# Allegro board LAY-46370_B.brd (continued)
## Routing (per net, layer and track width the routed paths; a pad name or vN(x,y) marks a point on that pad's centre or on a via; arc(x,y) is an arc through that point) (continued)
SAI3_TXD: length 92.5
  TOP w0.102: J4.25 116.58,67 v1(117.27,67.7)
  TOP w0.109: v1(192.31,37.28) 192.11,37.28 191.24,36.42 R193.1
  BOTTOM w0.109: v1(117.27,67.7) 117.77,67.2 127.79,67.2 148.33,46.66 183.76,46.66 192.31,38.1 v1(192.31,37.28)
SAI3_TXFS: length 93.1
  TOP w0.102: v1(117.99,67.68) 116.91,66.6 J4.23
  TOP w0.109: R192.1 v1(192.3,36.7)
  BOTTOM w0.109: v1(192.3,36.7) 192.34,36.7 192.81,37.17 192.81,38.2 184.02,46.99 148.61,46.99 127.75,67.85 118.15,67.85 v1(117.99,67.68)
SAI5_RX3: length 20.2
  TOP w0.102: v1(127.83,63.65) 127.52,63.34 116.42,63.34 116.35,63.41 J4.7 ; U54.1 v1(127.89,57.17)
  L6_IN2 w0.114: v1(127.89,57.17) 127.89,63.58 v1(127.83,63.65)
SAI5_RXC: length 77.4
  TOP w0.109: J4.4 113.35,62.6 113.46,62.49 113.46,57.56 117.47,53.55 136.78,53.55 139.65,56.41 171.31,56.41 176.65,51.08 178.42,51.08 TP86.1 178.69,49.75 R297.1
SAI5_RXD0: length 67.4
  TOP w0.109: J4.1 121.55,62.2 TP82.1 128.78,61.25 131.78,61.25 135.06,57.97 173.49,57.97 174.03,58.51 175.59,58.51 176.77,59.69 R293.1
SAI5_RXD1: length 67
  TOP w0.109: J4.3 122.68,62.6 TP83.1 127.88,61.88 145.29,61.88 148.11,59.06 175.31,59.06 v1(175.36,59.01) ; R294.1 178.28,58.46 175.88,58.46 v1(175.36,57.93)
  L6_IN2 w0.127: v1(175.36,57.93) v1(175.36,59.01)
SAI5_RXD2: length 68.1
  TOP w0.109: v1(175.95,56.94) 176.17,57.15 R295.1 ; J4.5 123.8,63 TP84.1 126.97,62.5 145.31,62.5 148.31,59.49 175.57,59.49 v1(175.95,59.88)
  L6_IN2 w0.127: v1(175.95,56.94) v1(175.95,59.88)
SAI5_RXD3: length 55.4
  TOP w0.109: R296.1 173.32,55.88 171.82,57.39 134.24,57.39 132.74,55.89 130.43,55.89 130.06,56.26 ; 130.06,56.26 129.69,55.89 126.35,55.89 TP85.1 ; 130.06,56.26 U54.2
SAI5_RXFS: length 79.8
  TOP w0.109: U58.5 177.59,48.69 170.24,56.05 139.87,56.05 136.92,53.09 117.14,53.09 112.87,57.37 J4.2
SD1_DATA4: length 48.1
  TOP w0.109: J2.91 112.73,107.1 112.86,106.97 112.86,103.12 106.99,97.25 106.99,89.89 v1(109.06,87.83)
  BOTTOM w0.109: U3.3 131.54,84.43 130.88,83.77 121.92,83.77 121.26,84.43 116.72,84.43 113.07,88.07 109.3,88.07 v1(109.06,87.83)
SD1_DATA5: length 47.3
  TOP w0.109: J2.93 113.13,102.83 107.41,97.11 107.41,90.11 v1(109.04,88.48)
  BOTTOM w0.109: v1(109.04,88.48) 113.04,88.48 116.64,84.88 129.99,84.88 130.1,84.77 R41.2 130.9,84.3 131.53,84.93 U3.4
SD2_CLK: length 99.5
  TOP w0.109: v1(150.2,127.91) 150.2,127.79 149.91,127.5 148.93,127.5 148.93,127.5 148.21,127.5 111.28,90.57 111.28,81.36 111.63,81 J4.96
  BOTTOM w0.109: R155.1 179.1,129.05 177.49,127.43 150.68,127.43 v1(150.2,127.91)
SD2_CMD: length 101.2
  TOP w0.109: v1(148.48,127.07) 148.24,127.07 112.54,91.37 112.54,87.69 112.22,87.37 112.22,81.55 112.36,81.4 J4.98
  BOTTOM w0.109: R154.1 184.72,131.72 180.12,127.12 148.53,127.12 v1(148.48,127.07)
SD2_DATA0: length 97.9
  TOP w0.109: J4.91 117.12,80.2 118.16,81.25 118.16,94.46 v1(151.64,127.94)
  BOTTOM w0.109: v1(151.64,127.94) 177.39,127.94 178.02,128.57 178.02,129.35 177.92,129.45 177.6,129.45 177.5,129.55 177.5,129.75 177.6,129.86 177.92,129.86 178.02,129.96 178.02,130.16 177.92,130.26 177.6,130.26 177.5,130.36 177.5,130.57 177.6,130.67 177.92,130.67 178.02,130.77 178.02,130.97 177.92,131.07 177.6,131.07 177.5,131.18 177.5,131.38 177.6,131.48 177.92,131.48 178.02,131.58 178.02,131.79 177.92,131.89 177.6,131.89 177.5,131.99 177.5,132.19 177.6,132.29 177.92,132.29 178.02,132.4 R156.1
SD2_DATA1: length 97.9
  TOP w0.109: v1(150.95,127.95) 150.95,127.64 117.8,94.49 117.8,81.43 116.98,80.6 J4.93
  BOTTOM w0.109: R157.1 176.95,130.67 176.79,130.5 176.43,130.5 175.53,131.4 175.39,131.4 175.24,131.26 175.24,131.11 176.14,130.22 176.14,130.07 176,129.93 175.85,129.93 174.96,130.83 174.81,130.83 174.67,130.68 174.67,130.54 175.56,129.64 175.56,129.19 174.76,128.39 151.39,128.39 v1(150.95,127.95)
SD2_DATA2: length 101.1
  TOP w0.109: v1(148.46,125.83) 148.23,125.83 117.45,95.04 117.45,81.53 116.92,81 J4.95
  BOTTOM w0.109: R158.1 186.88,132.44 180.97,126.53 150.68,126.53 149.97,125.83 v1(148.46,125.83)
SD2_DATA3: length 100.2
  TOP w0.109: J4.97 116.92,81.4 117.14,81.63 117.14,95.36 148.19,126.41 v1(148.47,126.41)
  BOTTOM w0.109: R159.1 185.81,131.98 180.66,126.83 148.91,126.83 148.49,126.41 v1(148.47,126.41)
SD2_NCD: length 104
  TOP w0.102: TP40.1 v1(149.2,128.81)
  TOP w0.109: J4.94 111.56,80.6 110.91,81.25 110.91,90.7 148.17,127.96 TP40.1
  BOTTOM w0.109: J11.9 175.59,134.46 TVS1.2 174.81,134.35 174.28,133.82 174.28,129.17 173.92,128.81 168.63,128.81 168.53,128.92 168.53,129.31 168.43,129.41 168.22,129.41 168.12,129.31 168.12,128.92 168.02,128.81 167.82,128.81 167.72,128.92 167.72,129.31 167.61,129.41 167.41,129.41 167.31,129.31 167.31,128.92 167.21,128.81 167.01,128.81 166.9,128.92 166.9,129.31 166.8,129.41 166.6,129.41 166.5,129.31 166.5,128.99 166.4,128.89 149.27,128.89 v1(149.2,128.81)
SD2_RESET_B: length 2
  TOP w0.102: TP62.1 117.25,79.25 116.48,79.25 116.32,79.4 J4.87
SPDIF_EXT_CLK: length 38
  TOP w0.102: v1(115.26,88.41) 113.88,87.04 113.88,69.2 113.68,69 J4.36
  BOTTOM w0.109: U3.9 116.15,87.43 115.26,88.32 v1(115.26,88.41)
SPDIF_RX: length 21.7
  TOP w0.102: J4.34 113.8,68.6 114.15,68.95 114.15,82.6 v1(114.39,82.83)
  BOTTOM w0.102: v1(114.39,82.83) 114.35,82.87 110.49,82.87 TP12.1 109.97,82.56 109.97,83.71 110.07,83.82 U52.4
SPDIF_TX: length 21.3
  TOP w0.102: J4.32 114,68.2 114.39,68.59 114.39,82 115.3,82.91 v1(115.3,84.09)
  BOTTOM w0.102: U52.1 113.01,84.15 TP11.1 115.24,84.15 v1(115.3,84.09)
SPK_LN: length 3.2
  TOP w0.203: R208.1 187.16,27.18 188.8,28.82 U50.23
SPK_LP: length 4.1
  TOP w0.203: R206.1 188.65,25.28 190.21,26.84 U50.25
SPK_RN: length 2.7
  TOP w0.203: U50.19 189,30.82 188.85,30.97 187.42,30.97 R203.1
SPK_RP: length 2.9
  TOP w0.203: U50.22 188.83,29.32 187.76,28.25 R202.1
SPKOUTLN: length 7.7
  TOP w0.203: R208.2 185.3,27.18 C201.1 185.29,26.74 185.1,26.55 183.89,26.55 183.24,27.2 C199.2 182.07,27.2 CON1.4
SPKOUTLP: length 18.8
  TOP w0.203: C198.2 188.66,23.49 R206.2 188.48,23.51 185.91,26.08 183.52,26.08 183.15,26.45 C199.1 182.47,26.45 182.15,26.13 182.15,24.69 181.38,23.92 179.82,23.92 178.72,25.02 178.72,26.4 CON1.3
SPKOUTRN: length 6.9
  TOP w0.203: CON1.2 180.49,30.17 C195.2 183.71,30.17 183.96,29.92 185.06,29.92 185.24,30.11 C196.1 185.26,30.63 R203.2
SPKOUTRP: length 12.8
  TOP w0.203: R202.2 186.33,28.25 C194.2 185.29,29 184.88,29.42 C195.1 181.32,29.42 181.08,29.18 179.28,29.18 178.68,29.79 178.68,31.44 CON1.1
SS_RXN1: length 8.7
  TOP w0.102: U18.1 50.32,18.07 50.24,18.15 50.24,18.34 50.35,18.44 51.18,18.44 51.72,17.91 51.72,14.63 51.09,14 50.34,14 49.89,13.55 49.89,13.18 49.69,12.98 49.69,12.94 49.6,12.84 U19.C2
SS_RXN2: length 8.8
  TOP w0.102: v1(48.58,13.34) 48.72,13.19 48.72,12.85 U19.C4 ; U18.16 51.16,17.25 v1(51.22,17.3)
  BOTTOM w0.102: v1(48.58,13.34) 48.58,13.43 48.74,13.58 48.74,13.92 48.96,14.15 50.88,14.15 51.19,14.46 51.19,15.09 50.21,16.07 50.21,16.92 50.57,17.28 50.86,17.28 50.88,17.3 v1(51.22,17.3)
SS_RXP1: length 9.4
  TOP w0.102: U18.2 49.92,18.07 50.03,18.17 50.03,18.43 50.26,18.66 51.27,18.66 51.93,18 51.93,14.54 51.18,13.79 50.43,13.79 50.11,13.46 50.11,12.89 U19.C1
SS_RXP2: length 8.7
  TOP w0.102: v1(51.22,16.67) 51.16,16.67 50.98,16.85 U18.15 ; v1(49.16,13.34) 49.05,13.22 49.05,13.01 49.2,12.86 U19.C3
  BOTTOM w0.102: v1(49.16,13.34) 49.16,13.42 48.95,13.63 48.95,13.83 49.05,13.93 50.97,13.93 51.41,14.37 51.41,15.18 50.43,16.16 50.43,16.83 50.66,17.06 50.83,17.06 v1(51.22,16.67)
SS_TXN1: length 5.2
  TOP w0.102: v1(46.29,13.4) 46.29,13.34 46.23,13.29 U16.C3 ; v1(45.38,16.71) 45.8,16.71 C48.1
  BOTTOM w0.102: v1(46.29,13.4) 46.29,13.51 46.1,13.69 46.1,16.29 45.88,16.51 45.58,16.51 v1(45.38,16.71)
SS_TXN2: length 9.5
  TOP w0.102: C53.1 46.02,18.5 45.93,18.59 45.32,18.59 44.72,17.98 44.72,15.18 45.09,14.81 46.81,14.81 47.31,14.31 47.31,13.65 46.94,13.28 46.94,13.03 46.95,13.03 46.95,13.02 47.03,12.93 U16.C1
SS_TXP1: length 5.1
  TOP w0.102: v1(45.7,13.4) 45.9,13.2 45.9,12.9 U16.C4 ; v1(45.36,16.13) 45.51,16.27 45.68,16.27 46.03,15.93 C50.1
  BOTTOM w0.102: v1(45.36,16.13) 45.53,16.3 45.79,16.3 45.89,16.2 45.89,13.69 45.7,13.51 v1(45.7,13.4)
SS_TXP2: length 9.5
  TOP w0.102: C52.1 45.74,18.8 45.23,18.8 44.5,18.07 44.5,15.09 45,14.59 46.72,14.59 47.09,14.22 47.09,13.74 46.72,13.37 46.72,13.02 46.63,12.93 U16.C2
SSRXN1: length 15.7
  TOP w0.102: v1(50.08,10.34) 50.08,10.41 50.29,10.61 50.29,10.76 49.78,11.27 49.78,11.73 49.6,11.91 U19.A2
  BOTTOM w0.102: J6.B10 43.17,5.94 43.17,5.45 43.39,5.23 49.52,5.23 50.66,6.38 50.66,8.19 50.29,8.57 50.29,9.31 50.2,9.4 50.01,9.4 49.92,9.49 49.92,9.67 50.01,9.76 50.2,9.76 50.29,9.85 50.29,10.08 50.08,10.29 v1(50.08,10.34)
SSRXN2: length 4.8
  TOP w0.102: U19.A4 48.8,11.85 48.88,11.76 48.88,11.6 48.89,11.6 48.89,10.98 46.98,9.07 46.98,8.75 46.83,8.61 J6.A10
SSRXP1: length 15.8
  TOP w0.102: U19.A1 50,11.35 50.5,10.85 50.5,10.56 50.67,10.4 v1(50.67,10.34)
  BOTTOM w0.102: v1(50.67,10.34) 50.51,10.18 50.51,8.66 50.88,8.28 50.88,6.29 49.61,5.02 43.3,5.02 42.96,5.36 42.96,5.98 J6.B11
SSRXP2: length 4.8
  TOP w0.102: J6.A11 47.33,8.61 47.19,8.75 47.19,8.98 49.1,10.89 49.1,11.6 49.11,11.6 49.11,11.81 49.2,11.9 U19.A3
SSTXN1: length 6.4
  TOP w0.102: v1(46.3,11.3) 46.17,11.43 46.17,11.83 46.23,11.89 U16.A3 ; v1(43.44,8.99) 43.25,8.8 43.25,8.45 43.33,8.37 J6.A3
  BOTTOM w0.102: v1(43.44,8.99) 43.26,9.18 43.26,9.58 43.8,10.13 45.34,10.13 46.12,10.9 46.12,11.12 v1(46.3,11.3)
SSTXN2: length 9.4
  TOP w0.102: v1(47.13,10.46) 46.95,10.64 46.95,11.77 47.03,11.86 U16.A1
  BOTTOM w0.102: v1(47.13,10.46) 47.13,10.61 46.96,10.78 46.96,11.37 47.04,11.46 47.91,11.46 48,11.37 48,8.6 46.98,7.58 46.98,6.54 J6.B3
SSTXP1: length 6.4
  TOP w0.102: v1(42.86,8.99) 42.96,8.89 42.96,8.42 42.83,8.3 J6.A2 ; v1(45.72,11.3) 45.89,11.48 45.89,11.87 45.83,11.93 U16.A4
  BOTTOM w0.102: v1(42.86,8.99) 43.04,9.17 43.04,9.67 43.71,10.34 45.25,10.34 45.9,10.99 45.9,11.12 v1(45.72,11.3)
SSTXP2: length 10.2
  TOP w0.102: U16.A2 46.63,11.86 46.73,11.76 46.73,10.65 v1(46.54,10.46)
  BOTTOM w0.102: J6.B2 47.19,6.54 47.19,7.49 48.21,8.51 48.21,11.46 48,11.68 46.95,11.68 46.74,11.46 46.74,10.78 46.54,10.59 v1(46.54,10.46)
ST_FT_USB_DN: length 6.3
  TOP w0.102: U60.7 12.27,14.79 12.42,14.65 12.42,14.25 12.82,13.84 12.82,12.33 13.24,11.91 14.47,11.91 14.6,11.78 14.6,11.62 R327.2
ST_FT_USB_DP: length 6.4
  TOP w0.102: R328.2 15.21,11.21 14.82,11.61 14.82,11.87 14.56,12.12 13.33,12.12 13.03,12.42 13.03,13.93 12.63,14.34 12.63,14.65 12.77,14.79 U60.8
SUSCLK_3V3: length 16.8
  TOP w0.254: v1(137.93,86.75) 138.08,86.75 138.15,86.68 TP99.1 138.8,87.7 139.44,88.35 151.24,88.35 v1(151.45,88.55)
  BOTTOM w0.254: v1(151.45,88.55) 151.47,88.58 J10.50 ; R30.1 137.85,86.67 v1(137.93,86.75)
SW_BOOT_MODE0: length 57.3
  TOP w0.109: SW4.4 8.91,125.27 R287.1 8.5,125.26 8.4,125.16 8.4,81.51 6.75,79.86 6.75,77.41 8.02,76.14 11.07,76.14 v1(11.2,76)
  BOTTOM w0.109: U20.16 10.98,77.15 11.2,76.93 v1(11.2,76)
SW_BOOT_MODE1: length 56.7
  TOP w0.109: SW4.3 7.64,125.27 R288.1 7.99,125.25 8.13,125.11 8.13,81.9 6.38,80.15 6.38,77.13 7.83,75.68 v1(9.75,75.68)
  BOTTOM w0.109: U20.3 9.57,75.86 v1(9.75,75.68)
SW_BOOT_MODE2: length 49.8
  TOP w0.109: v1(7.37,82.18) 7.37,82.42 5.84,83.96 5.84,125.15 5.96,125.27 R289.1 6.37,125.27 SW4.2
  BOTTOM w0.109: v1(7.37,82.18) 9.17,80.38 U20.9
SW_BOOT_MODE3: length 52.2
  TOP w0.109: SW4.1 5.1,125.26 R290.1 5.45,125.25 5.59,125.12 5.59,83.41 6.73,82.27 v1(6.73,82.21)
  BOTTOM w0.109: U20.12 10.37,79.59 10.54,79.76 10.54,80.71 8.58,82.67 7.19,82.67 v1(6.73,82.21)
SYS_NRST: length 187.5
  TOP w0.102: R406.2 12.82,133.28 12.96,133.14 D23.A
  TOP w0.109: v1(22.65,133.08) 21.54,134.19 15.7,134.19 14.65,133.14 D23.A ; J3.43 97.42,59.78 97.57,59.64 97.57,55.27 TP121.1 88.17,45.87 v1(88.17,45.66)
  L6_IN2 w0.114: v1(21.84,45.94) 21.84,55.74 24.02,57.92 v1(24.02,74.59) 25.07,75.64 25.07,118.29 24.53,118.83 24.53,126.06 22.57,128.02 22.57,133 v1(22.65,133.08)
  BOTTOM w0.102: v1(24.02,74.59) 23.93,74.5 R436.2
  BOTTOM w0.109: v1(88.17,45.66) 87.93,45.9 74.45,45.9 73.52,44.97 22.81,44.97 v1(21.84,45.94)
TCPC_NINT: length 116.9
  TOP w0.109: U11.10 29.85,18.72 v1(29.77,18.8) 29.59,18.8 TP22.1 ; v1(106.69,47.84) 107.47,48.63 107.47,58.54 107.02,58.99 J3.91
  L6_IN2 w0.114: v1(29.77,18.8) 29.77,22.51 37.01,29.75 v1(37.01,47.41)
  BOTTOM w0.109: v1(37.01,47.41) 37.44,47.84 106.69,47.84 v1(106.69,47.84)
TCPC_NINT1: length 100.4
  TOP w0.109: J3.93 107.42,59.91 107.28,59.76 107.28,59.3 107.83,58.74 107.83,48.27 v1(107.4,47.83) ; v1(41.53,29.96) 41.91,29.58 TP31.1 42.8,27.93 42.8,27.3 42.97,27.13 U17.10
  L6_IN2 w0.114: v1(41.53,47.34) v1(41.53,29.96)
  BOTTOM w0.109: v1(41.53,47.34) 106.9,47.34 v1(107.4,47.83)
TYPEC_EN_B: length 1.9
  TOP w0.102: U18.3 49.52,18.56 R40.1
UART2_RXD: length 117.6
  TOP w0.109: v1(76.51,45.42) 76.51,60.29 84.84,68.62 99.4,68.62 101.42,66.59 J3.64 ; R232.1 10.69,40.72 TP58.1 v1(10.33,42.11)
  BOTTOM w0.109: v1(76.51,45.42) 76,44.91 75.18,44.91 74.64,44.37 12.59,44.37 v1(10.33,42.11)
UART2_TXD: length 113.9
  TOP w0.109: R230.1 12.85,40.54 TP57.1 v1(13.38,42.11) ; J3.62 101.02,63.69 101.13,63.79 101.13,66.32 99.27,68.19 85.17,68.19 77.03,60.05 77.03,45.12 v1(76.5,44.59)
  BOTTOM w0.109: v1(76.5,44.59) 75.65,43.73 15,43.73 v1(13.38,42.11)
UART3_CTS: length 82.2
  TOP w0.102: J4.42 112.52,70.2 112.43,70.3 111.87,70.3 111.55,69.98 v1(111.55,69.82)
  TOP w0.109: U56.4 181.07,93.29 180.96,93.19 179.86,93.19 v1(179.09,92.41)
  BOTTOM w0.109: v1(111.55,69.82) 111.55,69.69 111.89,69.35 154.56,69.35 177.62,92.41 v1(179.09,92.41)
UART3_CTS_3V3: length 8.2
  TOP w0.109: J21.7 188.57,95.34 186.52,93.29 U56.8
UART3_RTS: length 83.7
  TOP w0.102: v1(110.97,69.82) 110.97,70.07 111.5,70.6 J4.44
  TOP w0.109: U56.5 180.21,92.89 v1(179.7,92.37)
  BOTTOM w0.109: v1(179.7,92.37) 178.97,91.64 177.54,91.64 154.86,68.96 111.71,68.96 110.97,69.7 v1(110.97,69.82)
UART3_RTS_3V3: length 8.5
  TOP w0.109: J21.11 186.19,90.26 183.55,92.89 U56.7
UART3_RXD: length 82.4
  TOP w0.102: v1(111.55,71.66) 111.59,71.66 112,71.25 112.31,71.25 112.47,71.4 J4.48
  TOP w0.109: U56.3 181.12,93.69 180.89,93.46 179.68,93.46 v1(179.23,93.91)
  BOTTOM w0.109: v1(179.23,93.91) 177.82,93.91 154.47,70.56 112.68,70.56 111.57,71.66 v1(111.55,71.66)
UART3_RXD_3V3: length 15.8
  TOP w0.109: J21.10 194.47,92.8 193.41,93.85 193.41,95.54 192.67,96.28 188.81,96.28 186.22,93.69 U56.9
UART3_TXD: length 83
  TOP w0.102: J4.46 111.28,71 v1(111.01,70.73)
  TOP w0.109: U56.2 180.95,94.09 180.91,94.05 v1(180,94.05)
  BOTTOM w0.109: v1(111.01,70.73) 111.95,70.73 112.43,70.25 154.92,70.25 178.12,93.46 179.4,93.46 v1(180,94.05)
UART3_TXD_3V3: length 13.9
  TOP w0.109: U56.10 185.95,94.09 188.49,96.63 193.11,96.63 194.4,95.34 J21.8
UART4_RXD: length 121.2
  TOP w0.109: v1(8.81,42.11) TP61.1 9.6,40.28 R233.1 ; J3.68 102.22,66.93 99.73,69.42 84.18,69.42 75.44,60.68 v1(75.44,45.41)
  BOTTOM w0.109: v1(75.44,45.41) 75.24,45.41 74.51,44.67 11.37,44.67 v1(8.81,42.11)
UART4_TXD: length 117.2
  TOP w0.109: v1(11.86,42.11) TP60.1 11.78,40.99 R231.1 ; J3.66 101.82,66.76 99.56,69.02 84.45,69.02 75.96,60.53 75.96,44.93 v1(75.48,44.45)
  BOTTOM w0.109: v1(75.48,44.45) 75.07,44.04 13.78,44.04 v1(11.86,42.11)
USB1_CC1: length 18.4
  TOP w0.109: U15.A2 40.62,12.39 40.02,12.99 40.02,15.45 40.58,16.02 42.23,16.02 42.69,16.47 42.69,21.17 41.7,22.16 TP28.1 42.18,24.87 43.15,24.87 43.62,25.34 U17.13
USB1_CC1_CN: length 6.4
  TOP w0.109: J6.A5 44.33,8.5 44.53,8.69 44.53,9.45 43.35,10.63 41.71,10.63 41.18,11.16 41.18,11.83 U15.A1
USB1_CC2: length 17.3
  TOP w0.109: U17.14 44.47,25.06 43.8,24.39 TP30.1 42.42,23.29 42.42,22.08 43.08,21.42 43.08,15.37 43.34,15.11 43.34,12.13 42.74,11.53 42.33,11.53 42.14,11.71 U15.C1
  TOP w0.203: U15.C1 U15.C2 U15.B2
USB1_CC2_CN: length 17.1
  TOP w0.102: U15.B1 41.72,11.97 v1(41.72,11.47)
  L3_IN1 w0.114: J6.B5 45.88,4.12 45.12,3.35 41.65,3.35 39.53,5.47 39.53,8.23 41.72,10.41 v1(41.72,11.47)
USB1_DN: length 120
  TOP w0.102: v1(77.83,111.99) 78.02,111.81 78.02,111.05 77.89,110.92 J1.36 ; U75.C1 44.56,12.95 44.42,13.08 44.42,13.51 44.49,13.58 44.71,13.58 44.81,13.68 v1(44.81,13.9)
  L6_IN2 w0.089: v1(77.83,111.99) 78.07,112.23 78.07,112.53 77.97,112.63 77.54,112.63 77.08,112.16 77.08,110.08 75.88,108.89 75.88,105.29 75.31,104.71 69.85,104.71 61.26,96.12 61.26,59.18 47.67,45.59 47.67,22.61 44.44,19.39 44.44,14.37 44.53,14.28 44.73,14.28 44.81,14.2 v1(44.81,13.9)
USB1_DN_CN: length 6.4
  TOP w0.102: J6.A7 45.33,8.79 v1(45.34,8.8) 45.34,9.99 44.56,10.77 U75.A1
  L3_IN1 w0.114: v1(45.34,8.8) 45.34,7.76 44.68,7.1 J6.B7
USB1_DP: length 120.1
  TOP w0.102: U75.C2 44.16,13.83 v1(44.23,13.9) ; v1(78.42,112) 78.23,111.81 78.23,111.25 78.29,111.2 J1.38
  L6_IN2 w0.089: v1(78.42,112) 78.29,112.13 78.29,112.62 78.06,112.84 77.45,112.84 76.86,112.25 76.86,110.17 75.67,108.98 75.67,105.37 75.22,104.93 69.76,104.93 61.04,96.21 61.04,59.27 47.45,45.68 47.45,22.7 44.23,19.48 v1(44.23,13.9)
USB1_DP_CN: length 6.5
  TOP w0.102: J6.B6 45.55,6.95 45.77,7.18 45.77,7.35 45.63,7.49 44.95,7.49 44.83,7.6 J6.A6 44.83,8.94 45.12,9.23 45.12,9.9 44.34,10.68 44.34,11.76 44.16,11.94 U75.A2
USB1_OTG_VBUS: length 2.3
  TOP w0.254: J6.B4 46.33,7 J6.A9 ; J6.A4 43.83,7 J6.B9
  vias: v1(40.1,11.41) v1(40.1,10.64) v1(40.1,9.76)
USB1_OTG_VBUS_F: length 0.9
  TOP w0.254: U17.15 44.87,24.75 v1(44.97,24.65)
  vias: v1(36.53,14.19) v1(36.52,13.51) v1(37.44,14.17) v1(37.44,13.52) v1(56.41,36.93) v1(57.05,36.91) v1(57.7,36.9) v1(58.33,36.91) v1(72.42,35.35) v1(72.42,34.72) v1(72.44,34.08)
USB1_RXN: length 113.9
  TOP w0.102: v1(50.41,15.15) 50.32,15.23 U18.14 ; v1(76.61,106.25) 76.79,106.42 76.79,107.13 76.69,107.22 J1.29
  L6_IN2 w0.089: v1(76.61,106.25) 76.61,104.76 75.96,104.11 70.42,104.11 62.31,96 62.31,58.64 48.78,45.11 48.78,19.95 47.04,18.21 47.04,15.17 48.28,13.92 49.84,13.92 50.29,14.38 50.29,15.03 50.41,15.15 v1(50.41,15.15)
USB1_RXP: length 113.8
  TOP w0.102: v1(77.2,106.25) 76.99,106.46 76.99,107.15 77.09,107.25 J1.31 ; v1(49.82,15.13) 49.82,15.21 50.11,15.5 50.11,15.76 49.92,15.94 U18.13
  L6_IN2 w0.089: v1(49.82,15.13) 50.08,14.87 50.08,14.47 49.75,14.14 48.37,14.14 47.26,15.26 47.26,18.13 49,19.86 49,45.02 62.52,58.55 62.52,95.91 70.51,103.9 76.05,103.9 76.83,104.67 76.83,105.8 76.92,105.88 77.18,105.88 77.27,105.97 77.27,106.18 v1(77.2,106.25)
USB1_SBU1: length 1.5
  TOP w0.102: TP24.1 45.83,9.45 J6.A8
USB1_SBU2: length 8.5
  TOP w0.102: v1(44.3,3.93) 38.7,3.93 TP25.1
  L3_IN1 w0.114: v1(44.3,3.93) 44.3,6.24 J6.B8
USB1_SS_SEL: length 109.2
  TOP w0.102: U18.12 49.52,15.44 49.19,15.11 49.19,14.86 v1(47.82,13.49)
  TOP w0.109: J3.97 108.22,59.86 108.25,59.83 108.25,47.96 v1(108.14,47.85)
  L6_IN2 w0.114: v1(53.85,46.51) 53.22,45.89 53.22,16.19 49.93,12.89 48.39,12.89 47.82,13.46 v1(47.82,13.49)
  BOTTOM w0.102: R38.1 47.82,13.71 v1(47.82,13.49)
  BOTTOM w0.109: v1(108.14,47.85) 107.22,46.93 54.27,46.93 v1(53.85,46.51)
USB1_TXN: length 109.8
  TOP w0.102: v1(48.1,15.05) 48.1,15.07 48.31,15.27 48.31,15.82 48.32,15.84 U18.9 ; v1(77.81,105.03) 77.81,105.04 78.03,105.26 78.03,107.08 77.89,107.22 J1.35
  L6_IN2 w0.089: v1(77.81,105.03) 77.95,104.88 77.95,104.87 77.99,104.83 77.99,104.42 76.88,103.31 71.08,103.31 63.75,95.98 63.75,57.87 51.55,45.67 51.55,21.38 48.27,18.1 48.27,15.22 v1(48.1,15.05)
USB1_TXP: length 109.8
  TOP w0.102: v1(48.68,15.05) 48.52,15.21 48.52,15.73 48.72,15.93 U18.10 ; J1.37 78.29,107.06 78.24,107.01 78.24,105.18 v1(78.39,105.03)
  L6_IN2 w0.089: v1(78.39,105.03) 78.21,104.85 78.21,104.34 76.97,103.09 71.16,103.09 63.96,95.89 63.96,57.78 51.76,45.58 51.76,21.29 48.49,18.01 48.49,15.25 v1(48.68,15.05)
USB1_TYPEC_EN_B: length 138.4
  TOP w0.102: v1(111.51,79.82) 111.99,80.3 112.32,80.3 112.42,80.2 J4.92 ; v1(51.11,19.82) 50.82,20.11 R40.2
  L6_IN2 w0.114: v1(111.51,79.82) 111.51,79.54 114.76,76.3 122.39,76.3 123.01,75.68 123.01,49.41 122.44,48.84 122.44,30.27 116.76,24.59 113.29,24.59 v1(109.81,21.12)
  BOTTOM w0.109: v1(109.81,21.12) 108.53,19.83 72.2,19.83 70.73,21.31 52.61,21.31 v1(51.11,19.82)
USB1_VBUS_3V3: length 119.4
  TOP w0.203: v1(79.5,111.4) 79.49,111.39 J1.44
  TOP w0.381: U12.1 67.41,34.99 67.06,34.63 R48.2
  TOP w0.457: R48.2 65.93,33.98 v1(65.88,34.03)
  L6_IN2 w0.457: v1(45.48,43.24) 45.48,46.42 56.88,57.82 56.88,96.91 v1(68.09,108.12)
  BOTTOM w0.457: v1(68.09,108.12) 68.12,108.14 73.84,108.14 75.72,110.02 78.07,110.02 79.44,111.4 v1(79.5,111.4) ; v1(45.48,43.24) 64.5,43.24 65.88,41.86 v1(65.88,34.03)
USB1_VBUS_IN: length 7.5
  TOP w0.254: v1(56.26,28.22) C43.2
  L6_IN2 w0.254: v1(56.26,28.22) 55.57,28.91 v1(55.57,33.9)
  vias: v1(54.88,35.65) v1(54.89,34.89) v1(54.89,33.93) v1(55.51,35.62) v1(55.51,34.83)
USB2_DN: length 3.6
  TOP w0.102: J1.54 81.49,111.07 81.6,111.18 81.6,111.78 v1(81.45,111.93)
  BOTTOM w0.102: R301.1 81.6,111.25 81.6,111.77 81.58,111.79 81.58,111.8 v1(81.45,111.93) 81.45,112.38 R299.2
USB2_DP: length 3.6
  TOP w0.102: J1.56 81.89,111.12 81.82,111.19 81.82,111.71 v1(82.04,111.93)
  BOTTOM w0.102: R300.1 82.21,110.81 81.8,111.23 81.8,111.69 v1(82.04,111.93) 82.04,112.49 R298.2
USB2_H_DN: length 107.1
  TOP w0.102: U77.C1 65.64,21.14 65.55,21.23 65.55,21.83 65.74,22.02 v1(65.74,22.06)
  L6_IN2 w0.089: v1(68.15,98.21) 68,98.07 68,97.6 65.33,94.94 65.33,28.53 65.55,28.31 65.55,24.07 65.64,23.98 65.73,23.98 65.82,23.89 65.82,23.71 65.73,23.62 65.64,23.62 65.55,23.53 65.55,23.35 65.64,23.27 65.73,23.27 65.82,23.18 65.82,23 65.73,22.91 65.64,22.91 65.55,22.82 65.55,22.25 v1(65.74,22.06)
  BOTTOM w0.102: v1(68.15,98.21) 67.94,98.42 67.94,104.23 71,107.29 74.78,107.29 76.43,108.95 78.43,108.95 80.5,111.02 80.5,112.41 80.26,112.65 80.26,114.36 80.7,114.8 81.21,114.8 81.59,114.43 81.59,113.8 81.22,113.42 R299.1
USB2_H_DP: length 107.2
  TOP w0.102: U77.C2 65.24,21.14 65.33,21.22 65.33,21.37 65.34,21.39 65.34,21.88 v1(65.15,22.06)
  L6_IN2 w0.089: v1(67.56,98.21) 67.78,97.99 67.78,97.69 65.12,95.03 65.12,28.44 65.34,28.22 65.34,22.25 v1(65.15,22.06)
  BOTTOM w0.102: v1(67.56,98.21) 67.73,98.38 67.73,104.32 70.91,107.5 74.69,107.5 76.34,109.16 78.34,109.16 80.29,111.11 80.29,112.32 80.04,112.56 80.04,114.45 80.61,115.02 81.3,115.02 81.81,114.52 81.81,113.84 R298.1
USB2_H_TXN: length 3
  TOP w0.102: C60.1 69.14,22.39 69.14,21.94 69.03,21.83 68.23,21.83 67.95,21.55 67.95,21.4 67.95,21.39 67.95,21.24 67.86,21.15 U21.C2
USB2_H_TXP: length 3
  TOP w0.102: U21.C1 68.26,21.16 68.17,21.25 68.17,21.39 68.17,21.4 68.17,21.47 68.32,21.61 69.12,21.61 69.36,21.85 69.36,22.39 C59.1
USB2_HOST_VBUS: length 4.6
  TOP w0.254: v1(60.17,17.96) 59.82,17.61 56.42,17.61 TP103.1
  vias: v1(60.87,17.95) v1(61.55,17.94)
USB2_PWR_EN: length 113.7
  TOP w0.102: J1.16 73.89,111.48 73.4,111.97 v1(73.37,111.97)
  TOP w0.109: v1(46.48,28.81) 51.87,28.81 54.24,26.43 54.99,26.43 55.6,27.04 57.29,27.04 57.77,26.55 R302.1
  L6_IN2 w0.114: v1(46.48,28.81) 46.11,29.19 46.11,46.15 57.8,57.85 57.8,94.14 69.31,105.65 74.37,105.65 74.76,106.04 74.76,110.63 73.42,111.97 v1(73.37,111.97)
USB2_RXN: length 96.5
  TOP w0.102: v1(79.88,105.66) 79.8,105.66 79.18,106.29 79.18,106.92 79.09,107.02 J1.41 ; v1(66.97,22.58) 67.15,22.4 67.15,21.4 67.15,21.39 67.15,21.27 67.06,21.18 U21.C4
  L6_IN2 w0.089: v1(66.97,22.58) 67.15,22.77 67.15,95.75 73.94,102.53 79.33,102.53 80.4,103.6 80.4,105.78 80.31,105.87 80.09,105.87 v1(79.88,105.66)
USB2_RXP: length 96.4
  TOP w0.102: J1.43 79.49,107.02 79.4,106.92 79.4,106.38 79.62,106.15 79.8,106.15 79.89,106.24 v1(79.89,106.25) ; U21.C3 67.46,21.15 67.37,21.23 67.37,21.39 67.37,21.4 67.37,22.4 v1(67.55,22.58)
  L6_IN2 w0.089: v1(67.55,22.58) 67.37,22.77 67.37,95.66 74.03,102.32 79.42,102.32 80.62,103.52 80.62,105.87 80.4,106.09 80.06,106.09 v1(79.89,106.25)
USB2_TXN: length 93.6
  TOP w0.102: v1(68.89,25.06) 68.89,24.97 69.1,24.76 69.1,23.95 69.1,23.95 C60.2 ; J1.47 80.29,107.02 80.38,106.92 80.38,106.1 80.63,105.86 80.89,105.6 81.05,105.6 v1(81.1,105.65)
  L6_IN2 w0.089: v1(81.1,105.65) 81.24,105.79 81.48,105.79 81.6,105.68 81.6,103.73 79.63,101.76 74.68,101.76 69.07,96.16 69.07,25.24 v1(68.89,25.06)
USB2_TXP: length 93.6
  TOP w0.102: J1.49 80.69,107.02 80.6,106.92 80.6,106.19 80.72,106.07 80.97,106.07 81.09,106.2 v1(81.09,106.25) ; C59.2 69.31,24.04 69.31,24.9 v1(69.47,25.06)
  L6_IN2 w0.089: v1(69.47,25.06) 69.29,25.24 69.29,96.07 74.77,101.55 79.72,101.55 81.82,103.64 81.82,105.77 81.53,106.05 81.25,106.05 81.09,106.21 v1(81.09,106.25)
USB2_VBUS_3V3: length 3.3
  TOP w0.203: J1.50 80.69,111.06 80.6,111.15 80.6,111.92 81.09,112.41 81.66,112.41 R66.2
USB_CC1: length 11.3
  TOP w0.102: U10.A2 24.93,12.34 24.82,12.44 24.82,15.14 25.17,15.48 28.05,15.48 TP19.1
  TOP w0.109: TP19.1 30.94,17.01 U11.13
USB_CC1_CN: length 152.2
  TOP w0.102: J5.A5 28.22,9.12 v1(28.23,9.13)
  L6_IN2 w0.114: SW3.3 19.87,150.1 26.9,143.07 26.9,73.43 35.92,64.42 35.92,31.93 28.83,24.85 28.83,9.73 v1(28.23,9.13)
USB_CC1_ESD: length 149.6
  TOP w0.109: U10.A1 v1(24.78,11.3)
  L6_IN2 w0.114: SW3.2 20.6,147.6 26.24,141.96 26.24,73.26 35,64.5 35,32.38 28.23,25.61 28.23,12.72 27.35,11.84 25.31,11.84 v1(24.78,11.3)
USB_CC2: length 9.1
  TOP w0.109: U11.14 31.79,16.75 29.98,14.95 TP21.1 26.77,11.59 26.43,11.59 26.21,11.8 U10.C1 U10.C2 U10.B2
USB_CC2_CN: length 165.9
  L6_IN2 w0.114: SW3.6 17.41,151.14 20.02,151.14 27.25,143.91 27.25,73.47 36.33,64.4 36.33,31.32 29.14,24.13 29.14,15.08 34.37,9.85 34.37,6.82 32.91,5.36 30.66,5.36 J5.B5
USB_CC2_ESD: length 154.2
  TOP w0.109: v1(25.53,11.37) 25.81,11.65 U10.B1
  L6_IN2 w0.114: v1(25.53,11.37) 27.63,11.37 28.52,12.26 28.52,25.08 35.48,32.04 35.48,64.46 26.56,73.39 26.56,142.43 20.14,148.84 17.61,148.84 SW3.5
USB_DBG_DN: length 5
  TOP w0.102: U62.A2 14.66,8.15 14.66,7.38 13.82,6.54 13.51,6.54 12.67,5.7 12.67,5.12 12.46,4.91 J23.2
USB_DBG_DP: length 5
  TOP w0.102: J23.3 13.11,4.89 12.9,5.1 12.9,5.61 13.61,6.32 13.92,6.32 14.89,7.29 14.89,8.22 U62.A1
USB_HOST_DN: length 21.3
  TOP w0.102: U77.A1 65.64,20.06 65.55,19.98 65.55,18.91 63.25,16.6 59.11,16.6 57.75,15.24 57.75,12.98 58.83,11.9 62.91,11.9 63.21,12.19 63.21,13.15 62.97,13.4 62.37,13.4 J7.2
USB_HOST_DP: length 21.2
  TOP w0.102: J7.3 63.52,13.11 63.43,13.02 63.43,12.1 63,11.68 58.74,11.68 57.53,12.89 57.53,15.32 59.02,16.82 63.16,16.82 65.33,19 65.33,19.81 65.33,19.82 65.33,19.92 65.24,20.01 U77.A2
USB_HOST_RXN: length 10.8
  TOP w0.102: v1(66.2,17.68) 66.2,17.74 66.58,18.12 66.58,19.13 67.15,19.7 67.15,19.83 67.15,19.84 67.15,19.94 67.06,20.03 U21.A4
  BOTTOM w0.102: J7.5 66.38,14.61 66.15,14.84 66.15,15.52 65.09,16.58 65.09,16.73 65.18,16.82 65.28,16.82 65.37,16.9 65.37,17.08 65.28,17.17 65.18,17.17 65.09,17.26 65.09,18.15 65.61,18.67 66.42,18.67 66.56,18.53 66.56,18.09 66.2,17.73 v1(66.2,17.68)
USB_HOST_RXP: length 10.9
  TOP w0.102: v1(66.78,17.68) 66.79,17.69 66.79,19.04 67.37,19.61 67.37,19.83 67.37,19.84 67.37,19.98 67.46,20.07 U21.A3
  BOTTOM w0.102: v1(66.78,17.68) 66.79,17.69 66.79,18.67 66.57,18.89 65.52,18.89 64.87,18.24 64.87,16.49 65.94,15.43 65.94,14.8 65.74,14.61 J7.6
USB_HOST_TXN: length 14
  TOP w0.102: U21.A2 67.86,20.07 67.95,19.98 67.95,19.84 67.95,19.83 67.95,19.31 v1(67.78,19.13)
  BOTTOM w0.102: J7.8 60.4,14.61 60.22,14.79 60.22,15.64 64.53,19.95 65.23,19.95 65.32,19.86 65.32,19.82 65.41,19.73 65.59,19.73 65.68,19.82 65.68,19.86 65.77,19.95 65.94,19.95 66.03,19.86 66.03,19.81 66.12,19.72 66.3,19.72 66.39,19.81 66.39,19.86 66.48,19.95 66.66,19.95 66.74,19.86 66.74,19.81 66.83,19.72 67.01,19.72 67.1,19.81 67.1,19.86 67.19,19.95 67.77,19.95 67.96,19.75 67.96,19.32 v1(67.78,19.13)
USB_HOST_TXP: length 14.1
  TOP w0.102: v1(68.36,19.13) 68.17,19.33 68.17,19.83 68.17,19.84 68.17,20 68.26,20.09 U21.A1
  BOTTOM w0.102: v1(68.36,19.13) 68.18,19.32 68.18,19.84 67.85,20.16 64.44,20.16 60,15.73 60,14.78 59.84,14.61 J7.9
USB_LD_NFLT: length 1.8
  TOP w0.109: U11.11 29.27,18.32 R447.1
USB_LD_NFLT1: length 1.7
  TOP w0.109: U17.11 42.83,26.73 R63.1
USB_PWR_VBUS_F: length 12.7
  TOP w0.203: R42.1 25.04,21.83 25.31,21.56 29.36,21.56 31.77,23.96 31.77,25.09
  TOP w0.254: 32.18,15.54 32.19,15.54 U11.15
  vias: v1(32.82,23.3) v1(33.23,14.12) v1(33.22,13.47) v1(33.75,23.29) v1(34.16,14.11) v1(34.15,13.46) v1(34.56,23.28)
USB_SBU1: length 2
  TOP w0.102: TP14.1 29.72,10.01 J5.A8
USB_SBU2: length 8.8
  TOP w0.102: TP15.1 34.19,5.14 29.29,5.14 J5.B8
VEXP_3V3: length 12
  TOP w0.203: U57.11 183.09,60.69 C233.1 ; U58.11 183.13,51.52 C235.1 ; U55.11 183.26,77.62 C229.1
  TOP w0.254: U56.11 183.31,95.08 C231.1
  TOP w0.381: C229.1 v1(184.35,78.06) ; C235.1 v1(184.2,51.96) ; C231.1 v1(184.72,95.78) ; J21.17 v1(188.36,82.64) ; C233.1 v1(183.77,60.73)
  vias: v1(187.03,104.68) v1(187.08,101.06) v1(187.64,104.68) v1(187.69,101.06) v1(187.98,103.48) v1(187.96,102.87) v1(188.98,104.71) v1(189.59,104.71)
VEXT_3V3: length 32.2
  TOP w0.33: J15.A13 v1(130.44,133.56) ; J15.A14 v1(129.64,133.56) ; J16.A13 v1(106.44,133.56) ; J14.A14 v1(33.66,133.56) ; J12.A14 v1(57.66,133.56) ; J13.A14 v1(81.65,133.56) ; J16.A14 v1(105.64,133.56) ; J12.A13 v1(58.46,133.56) ; J13.A13 v1(82.45,133.56) ; J14.A13 v1(34.46,133.56)
  TOP w0.381: v1(184.67,103.46) L25.1 v1(185.58,104.31) ; J22.1 J22.2 192.88,124.89 C223.2 v1(195.5,124.25)
  BOTTOM w0.381: 126.63,81.18 128.84,81.18 129.9,80.13 133.36,80.13 R36.1
  BOTTOM w0.457: C276.2 45.35,108.34 v1(46.14,108.34) C275.1
  vias: v1(41.58,114.18) v1(41.61,113.35) v1(42.35,114.18) v1(42.37,113.35) v1(124.07,78.08) v1(124.41,79.07) v1(125.34,79.41) v1(125.64,80.39)
VEXT_3V3_EN: length 128.6
  TOP w0.102: v1(108.32,112.75) 108.32,112.92 104.38,116.86 73.83,116.86 69.32,112.35 69.32,109.97 67.32,107.96 67.32,105.48 v1(62.58,100.74)
  L3_IN1 w0.114: v1(62.58,100.74) 51.3,100.74 v1(51.3,100.75)
  L6_IN2 w0.114: v1(116.26,88.02) 116.96,88.72 116.96,100.26 113.05,104.17 113.05,108.01 v1(108.32,112.75)
  BOTTOM w0.102: R37.1 48.14,103.74 51.13,100.75 v1(51.3,100.75)
  BOTTOM w0.109: U3.16 136.91,87.43 137.69,88.21 137.69,89.21 136.27,90.64 129.62,90.64 127.01,88.02 v1(116.26,88.02)
VLDO1_3V3: length 2.9
  TOP w0.203: C47.1 57.67,31.74 58.53,32.6 U14.A5
VLDO_3V3: length 62.3
  TOP w0.203: C27.1 25.41,13.93 U10.A3 ; C45.1 41.34,14.04 U15.A3 ; U14.A1 61.19,31.69 C46.1
  TOP w0.381: v1(62.16,26.08) 62.16,30.06 61.78,30.44 C46.1 ; C45.1 v1(40.71,14.04) ; U13.5 43.9,20.72 C35.1 45.13,22.23 TP23.1 46.7,23.78 v1(46.7,24.51) ; C27.1 v1(26.16,13.93)
  L6_IN2 w0.508: v1(40.71,14.04) 41.04,14.04 41.41,14.42 41.41,18.16 46.7,23.44 v1(46.7,24.51)
  BOTTOM w0.381: v1(46.7,24.51) 55.33,24.51 56.14,25.32 61.4,25.32 v1(62.16,26.08) ; v1(40.71,14.04) 39.33,12.67 28.18,12.67 26.91,13.93 v1(26.16,13.93)
VPCIE_3V3: length 3
  TOP w0.381: TP104.1 143,87.76 v1(142.71,87.76)
  BOTTOM w0.381: R374.2 v1(160.23,83.11) ; R373.2 v1(163.93,83.18) ; R149.1 v1(157.1,85.9)
  vias: v1(128.47,75.52) v1(128.47,74.31) v1(129.66,75.53) v1(129.69,74.31) v1(130.95,75.56) v1(130.97,74.4) v1(142.1,87.76) v1(142.1,86.55) v1(142.11,85.33) v1(142.72,86.57) v1(142.75,85.28) v1(165.97,89.51) v1(166,88.25) v1(167.33,89.48) v1(167.31,88.24) v1(168.67,89.52) v1(168.68,88.22)
VSD_3V3: length 95.2
  TOP w1.27: 136.84,98.56 136.84,99.4 159.28,121.84 172.95,121.84 174.22,123.11 174.22,126.29 TP41.1
  L6_IN2 w1.27: 98.24,65.26 98.24,66.15 100.76,68.66 102.75,68.66 105.23,71.14 105.23,97.87 105.85,98.49
  vias: v1(97.23,64.52) v1(97.66,64.09) v1(106.76,99.73) v1(106.76,98.95) v1(135.75,98.61) v1(135.75,97.83) v1(180.79,135.11) v1(181.48,135.09)
VSYS_5V:
  vias: v1(87.83,63.71) v1(87.84,62.97) v1(87.86,60.78) v1(87.88,60.08) v1(88.46,63.71) v1(88.46,62.98) v1(88.5,60.77) v1(88.54,60.11)
VTREF: length 2.6
  TOP w0.254: R246.2 20.7,127.31 J24.1
WDOG_B: length 79.9
  TOP w0.109: J1.10 72.69,111.61 72.44,111.87 71.12,111.87 70.72,111.48 70.72,97.76 55.93,82.97 v1(23.18,82.97)
  BOTTOM w0.109: v1(23.18,82.97) 23.18,82.96 22.82,82.6 R437.2
N98831920: length 4
  BOTTOM w0.109: R155.2 179.1,134.83 179.99,135.71 J11.5
N101118683: length 3.7
  BOTTOM w0.109: J11.8 176.69,134.41 R157.2
N101118691: length 3.7
  BOTTOM w0.109: J11.7 177.79,134.37 R156.2
N101118780: length 4.7
  BOTTOM w0.109: J11.3 182.19,136.63 R154.2
N101118796: length 4.6
  BOTTOM w0.109: R158.2 184.39,136.61 J11.1
N101783582: length 4.6
  BOTTOM w0.109: R159.2 183.29,136.64 J11.2
N101995244: length 14.3
  TOP w0.254: v1(158.93,107.25) 159.2,107.52 U29.20 ; v1(159.15,112.49) 159.2,112.44 U29.11
  TOP w0.381: L10.2 v1(157.08,112.58)
  BOTTOM w0.381: C109.1 156.82,107.89 156.42,108.28 156.42,111.92 v1(157.08,112.58) 157.59,112.58 158.34,111.83 C108.1 159.2,112.44 v1(159.15,112.49) ; C109.1 158.65,107.53 v1(158.93,107.25) ; C109.1 159.72,107.89 C107.1
N101995252: length 4.8
  TOP w0.102: U29.2 163.47,109.09 C111.1
  TOP w0.109: Y3.3 165.15,108.44 163.8,108.44 163.67,108.57 C111.1
N101995256: length 6.4
  TOP w0.109: Y3.1 166.36,108.2 163.79,108.2 163.65,108.06 C110.1 163.34,107.71 162.46,108.59 U29.1
N101995353: length 14.5
  TOP w0.254: U29.16 157.22,109.59 v1(157.21,109.58) ; U29.3 v1(162.59,109.59)
  TOP w0.381: L9.1 165.67,111.06 164.15,109.53 162.65,109.53 v1(162.59,109.59)
  L3_IN1 w0.381: v1(157.21,109.58) 158.36,108.42 161.42,108.42 v1(162.59,109.59)
  BOTTOM w0.381: v1(157.21,109.58) 157.92,109.58 C104.1 ; v1(162.59,109.59) 162.17,109.17 C106.1 161.92,109.17 C105.1
N101995404: length 2.7
  TOP w0.102: R131.1 156.57,111.09 U29.13
N101995406: length 2.1
  TOP w0.102: TP36.1 163.86,110.09 U29.4
N101995408: length 2.4
  TOP w0.102: U29.14 155.76,110.59 R132.1
N101995436: length 2.5
  TOP w0.102: U29.17 155.91,109.09 R137.1
N101995453: length 2.5
  TOP w0.102: U29.18 156.05,108.59 R138.1
N101995643: length 2.8
  TOP w0.109: U29.19 158.7,107.74 157.7,106.75 R140.2
N101995645: length 1.8
  TOP w0.109: R139.2 158.7,113.1 U29.12
N101995688: length 2.7
  TOP w0.109: R141.2 160.7,106.24 U29.23
N103620610: length 5.5
  BOTTOM w0.381: TVS8.2 36.9,69.25 R252.2 36.9,69.24 D24.C 38.18,67.88 C265.1 39.29,67.88 R24.1
N103620806: length 4.8
  BOTTOM w0.254: R251.1 40.27,60.65 42.41,62.8 U63.8
N103620818: length 1.3
  BOTTOM w0.254: C254.1 39.54,58.03 R251.2
N103621273: length 3.9
  BOTTOM w0.203: R256.2 39.96,64.36 R254.2 39.95,65.47 R260.1
  BOTTOM w0.254: R260.1 40.66,65.48 41.09,65.04 U63.11
N103621294: length 2.7
  BOTTOM w0.254: U63.6 45.93,64.04 R259.1 45.99,62.89 R258.2
N104279466: length 1.9
  TOP w0.109: R133.2 160.7,112.99 U29.8
N104279469: length 1.9
  TOP w0.109: U29.9 160.2,112.18 160.37,112.35 160.37,113.08 R134.2
N104764716: length 5.6
  TOP w0.203: U29.5 v1(162.59,110.59)
  TOP w0.381: R147.2 164.79,112.27 163.12,110.59 v1(162.59,110.59)
  BOTTOM w0.381: R148.2 162.22,110.22 v1(162.59,110.59)
N105095140: length 2.7
  BOTTOM w0.114: C120.2 155.05,99.38 155.05,98.17 155.22,98 J10.35
N105095143: length 2.7
  BOTTOM w0.114: J10.37 154.72,97.95 154.84,98.06 154.83,98.07 154.83,99.25 C121.2
N106947509: length 5.7
  BOTTOM w0.381: Q8.4 56.87,100.06 56.25,100.69 C264.2 55.51,100.69 R261.2 54.37,101.79 R263.1 55.45,101.8 C261.2
N106947511: length 2.1
  BOTTOM w0.381: R263.2 Q10.3
N106947532: length 4.9
  BOTTOM w0.381: R264.2 R265.2 52.46,102.55 Q10.1 52.45,104.05 C269.1 R266.1
N107574242: length 8.3
  TOP w0.102: J22.3 J22.4 192.88,127.42 R221.2
N107574341: length 8.3
  TOP w0.102: R222.2 192.88,129.97 J22.6 J22.5
N107626870: length 7.9
  BOTTOM w0.203: R37.2 46.75,104.83 R271.2 46.75,104.83 C277.1 46.75,105.93 R272.1 46.17,107.61 44.83,107.61 44.6,107.38 R269.2 44.18,106.61 U64.5
N107626960: length 4.8
  BOTTOM w0.203: R273.1 43.31,110.78 C272.2 43.3,109.67 R268.2 43.3,109.2 42.15,108.05 U64.3
N107627021: length 1.7
  BOTTOM w0.254: U64.6 44.41,106.11 R267.2
N107627186: length 2.1
  BOTTOM w0.203: U64.4 43.37,107.11 C276.1
N107870832: length 6.2
  BOTTOM w0.254: R256.1 38.64,62.67 38.64,61.1 38.84,60.9 38.84,59.39 38.66,59.21 C256.1 R253.2
N107900649: length 2.8
  BOTTOM w0.254: U63.12 41.28,65.54 39.69,67.14 R24.2
N108223184: length 1.7
  TOP w0.381: C240.1 4.8,16.26 U59.4
N108629575: length 5.3
  TOP w0.305: J12.A8 62.46,133.66 62.34,133.78 v1(62.04,133.78) 61.96,133.78 61.66,133.47 J12.A9
  BOTTOM w0.305: TP43.1 62.04,134.21 v1(62.04,133.78)
N108650969: length 3
  TOP w0.203: U14.A6 56.26,30.87 C43.1
N108650998: length 2.5
  TOP w0.203: U14.A3 59.33,30.74 C44.1
N108651072: length 2.5
  TOP w0.203: R56.2 59.73,30.8 U14.A2
N108651079: length 2.3
  TOP w0.203: U14.E1 61.51,34.35 R57.2
N108651264: length 1.9
  TOP w0.109: U15.C3 42.14,12.97 42.35,13.18 42.35,14.05 TP26.1
N108688907: length 1.7
  TOP w0.203: U22.D4 59.83,24.85 C64.1
N108749685: length 2
  TOP w0.109: R188.2 190.71,33.73 U50.15
N108749687: length 3.4
  TOP w0.203: C175.1 191.21,24.33 U50.27
N108749719: length 2
  TOP w0.109: R192.2 191.71,33.68 U50.13
N108749740: length 2.3
  TOP w0.102: R191.2 193.28,34.26 192.21,33.2 U50.12
N108749771: length 2.2
  TOP w0.109: R194.2 190.21,33.18 U50.16
N108749815: length 1.8
  TOP w0.109: U50.14 191.21,34.24 R193.2
N108749834: length 2.9
  TOP w0.109: R195.2 193.96,33.79 193.22,33.79 192.71,33.28 U50.11
N108749893: length 1.6
  TOP w0.203: TP51.1 192.71,26.46 U50.30
N108750085: length 4.3
  TOP w0.203: R199.2 198.95,25.98 R200.1 C182.1
N108750181: length 9.6
  TOP w0.203: R200.2 200.18,26.44 201.07,26.44 201.28,26.65 201.28,29.49 v1(201.05,29.72) R201.1 ; C183.2 198.1,31.83 v1(198.14,31.79)
  BOTTOM w0.203: v1(198.14,31.79) 198.99,31.79 v1(201.05,29.72)
N108752359: length 3.6
  TOP w0.203: Q6.1 184.19,22.38 C197.2 R204.2 182.1,22.37 R205.1
N108752379: length 2.6
  TOP w0.203: Q7.3 181.01,19.17 R205.2
N108752409: length 3.6
  TOP w0.381: Q7.1 184.02,18.44 C200.1 185.39,18.71 R209.1 R207.2
N108779922: length 4.4
  TOP w0.203: U22.B1 U22.B2 ; U22.B1 U22.C1 ; U22.B1 58.83,20.26 D5.A
N108856282: length 4.2
  TOP w0.109: U23.39 98.68,27.26 98.58,27.16 98.31,27.16 97.7,26.55 97.7,25.06 R81.1
N108894167: length 2.5
  TOP w0.109: R79.1 104.77,27.66 U23.13
N108894170: length 2.2
  TOP w0.102: R80.1 105.75,28.06 U23.14
N108934835: length 6
  TOP w0.109: R112.1 78.6,23.1 79.24,23.74 79.24,26.86 79.67,27.29 U26.39
N108973788:
  vias: v1(30.58,10.89) v1(30.61,10.21) v1(30.63,9.52)
N108973950: length 2.5
  TOP w0.109: TP16.1 27.24,13.89 26.21,12.86 U10.C3
N108990768: length 2.1
  BOTTOM w0.102: R4.2 130.88,83.23 131.58,83.93 U3.2
N108992491: length 1.8
  TOP w0.203: R15.2 179.92,103.7 U5.12
N108999488: length 3.4
  TOP w0.381: C163.1 R2.2 25.17,19.27 R45.1 25.14,19.29 Q1.1
N109006824: length 2.5
  BOTTOM w0.203: C278.1 23.03,102.22 U49.10
N109006844: length 2.8
  BOTTOM w0.254: 22.48,101.24 22.63,101.09 U49.9
  BOTTOM w0.457: 22.48,101.24 22.48,101.47 21.92,102.03 C278.2
N109007030: length 4.6
  BOTTOM w0.203: C280.2 26.45,100.81 R276.2 26.45,98.61 R280.1 25.4,98.6 24.88,99.11 U49.14
N109010135: length 2.2
  BOTTOM w0.203: U49.4 19.76,98.71 R281.2
N109011918: length 1.6
  TOP w0.102: R270.2 4.2,139.39 D25.A
N109066072: length 13.2
  TOP w0.203: R210.2 v1(131.32,21.13)
  TOP w0.254: C207.1 138.59,20.29 R211.2 v1(139.47,20.28)
  L3_IN1 w0.114: v1(139.47,20.28) 139.46,20.28 137.81,18.64 133.24,18.64 131.32,20.56 v1(131.32,21.13)
N109088165: length 13.5
  TOP w0.203: R215.2 v1(169.53,22.3) ; R214.2 162.17,21.36 v1(161.27,21.36)
  TOP w0.254: R214.2 162.2,22.56 C215.1
  L3_IN1 w0.114: v1(161.27,21.36) 162.56,20.07 168.66,20.07 169.53,20.94 v1(169.53,22.3)
N109209998: length 4.8
  TOP w0.33: J13.A8 86.45,133.41 86.23,133.63 v1(85.92,133.63) 85.65,133.37 J13.A9
  BOTTOM w0.33: TP44.1 86.25,133.96 v1(85.92,133.63)
N109210079: length 10.1
  TOP w0.33: J13.A11 v1(84.05,133.56)
  TOP w0.381: v1(83.72,127.65) 83.2,127.14 R165.2
  L6_IN2 w0.381: v1(83.72,127.65) 84.29,128.23 84.29,133.3 84.05,133.55 v1(84.05,133.56)
  BOTTOM w0.109: v1(84.05,133.56) 84.05,132.75 R163.2
N109239152: length 1.8
  TOP w0.109: U48.2 163.93,126.55 R181.2
N109239179: length 2
  TOP w0.109: U48.3 164.46,125.9 R183.2
N109242668: length 2.3
  TOP w0.109: R185.1 171.25,125.25 U48.5
N109294186: length 4.7
  TOP w0.203: J14.A9 37.66,133.5 37.83,133.66 v1(38.24,133.66) 38.46,133.45 J14.A8
  BOTTOM w0.203: v1(38.24,133.66) 38.24,134.55 TP47.1
N109296461: length 2.7
  TOP w0.203: J14.A10 v1(36.86,133.62)
  BOTTOM w0.203: v1(36.86,133.62) 36.86,134.48 TP48.1
N109299410: length 2.7
  TOP w0.33: J15.A10 v1(132.84,133.56)
  BOTTOM w0.102: v1(132.84,133.56) 133.2,133.19 TP49.1
N109302474: length 3.4
  TOP w0.102: J16.B8 110.84,126.74 R168.1
N109302491: length 3.3
  TOP w0.102: J16.B9 110.04,126.49 R169.1
N109302514: length 2.1
  TOP w0.33: J16.A10 v1(108.84,133.56)
  BOTTOM w0.33: TP50.1 108.88,133.52 v1(108.84,133.56)
N109310681: length 3.7
  TOP w0.254: U53.1 135.54,37.32 U53.16 135.54,35.83 136.23,35.14 R218.2
N109310959: length 2.9
  TOP w0.203: U53.4 135.88,38.54 136.08,38.75 136.08,40.43 R216.2
N109310972: length 1.8
  TOP w0.203: U53.5 135.54,40.76 R217.2
N109373964: length 1.5
  TOP w0.102: U55.12 182.59,78.04 R223.2
N109397839: length 1.4
  TOP w0.203: R224.2 182.64,95.47 U56.12
N109400332: length 2
  TOP w0.102: U57.12 182.42,60.33 R225.2
N109402713: length 1.6
  TOP w0.109: U58.12 182.45,51.91 R226.2
N109415208: length 1.6
  BOTTOM w0.203: R27.2 109.21,93.75 U6.12
N109503700: length 2.9
  TOP w0.109: R293.2 180.62,58.41 U57.2
N109503714: length 2.6
  TOP w0.109: R294.2 179.75,58.01 U57.3
N109503728: length 2.6
  TOP w0.109: U57.4 179.78,57.61 R295.2
N109503742: length 3
  TOP w0.109: U57.5 180.65,57.21 R296.2
N109503902: length 2.5
  TOP w0.109: U58.2 179.85,49.89 R297.2
N109622186: length 196.9
  TOP w0.109: R406.1 13.23,134.95 24.26,134.95 29.63,129.58 v1(29.63,126.54) ; SW2.4 SW2.3 182.42,139.81 181.9,139.29 v1(172.9,139.29)
  BOTTOM w0.109: v1(29.63,126.54) 29.68,126.48 62.87,126.48 63.52,127.13 83.95,127.13 87.36,130.55 172.47,130.55 172.9,130.97 v1(172.9,139.29)
N109731195: length 2.7
  TOP w0.203: R312.2 118.93,30.89 118.53,31.29 U4.4
N109731201: length 1.5
  TOP w0.203: U4.5 120.45,31.78 R322.2
N109731216: length 2.1
  TOP w0.203: R323.2 116.01,31.47 116.32,31.78 U4.16 117.3,31.78 U4.1
N109737134: length 4.1
  TOP w0.254: L21.2 13.84,13.86 13.27,14.43 U60.9 v1(13.27,16.74)
  BOTTOM w0.381: v1(13.27,16.74) 13.26,16.75 C241.1
N109737207: length 3.9
  TOP w0.254: L22.2 10.77,14.02 U60.4 v1(10.77,16.74)
  BOTTOM w0.381: C242.1 10.79,16.76 v1(10.77,16.74)
N109737719: length 2.9
  TOP w0.109: R329.2 15.78,13.83 C251.1 U60.14
N109737725: length 2.4
  TOP w0.254: R330.1 12.22,13.62 11.77,14.07 U60.6
N109773309: length 2.1
  TOP w0.254: D20.A 10.6,31.18 R242.1
N109773326: length 1.6
  TOP w0.381: D21.A 3.72,24.19 R241.1
N109773834: length 2.7
  TOP w0.254: R235.1 11.91,32.63 12.93,31.6 13.16,31.6 D16.A
N109773857: length 2.4
  TOP w0.254: D17.A 11.36,31.96 10.98,31.96 R237.1
N109792630: length 1.5
  BOTTOM w0.203: R347.1 7.63,51.15 U8.13
N109864993: length 2.4
  TOP w0.381: D22.C 16.01,129.03 R245.1
N109865112: length 2.7
  TOP w0.109: R247.1 J24.7
N109865133: length 2.7
  TOP w0.109: R248.1 20.71,132.4 J24.9
N109916641: length 2.1
  BOTTOM w0.109: R427.1 12.08,78.77 U20.13
N109928082: length 3.2
  BOTTOM w0.102: R371.1 153.9,87.26 155.47,88.83 J10.34
N109928083: length 2.9
  BOTTOM w0.102: R370.1 155.97,88.31 J10.32
N109928084: length 3.8
  BOTTOM w0.102: R372.1 153.39,87.9 154.15,87.9 154.97,88.72 J10.36
N109928085: length 4.2
  BOTTOM w0.102: R369.1 156.81,88.06 157.96,88.06 158.47,88.57 J10.22
N109928213: length 3.1
  TOP w0.102: D30.A v1(162.92,86.02)
  BOTTOM w0.102: v1(162.92,86.02) 163.3,85.64 R373.1
N109928444: length 2.3
  TOP w0.102: D31.A v1(160.67,85.23)
  BOTTOM w0.102: R374.1 160.87,85.04 v1(160.67,85.23)
N109980953: length 2.6
  BOTTOM w0.203: Q11.1 21.96,48.27 R383.2 21.92,48.23 R382.2
N109981204: length 1.1
  BOTTOM w0.203: R381.1 21.32,52.55 Q11.3
N109995760: length 3
  TOP w0.381: C325.1 3.43,34.27 3.72,33.99 L23.1 4.14,33.96 U74.5
N109995782: length 1.6
  TOP w0.381: U74.4 6.04,34.15 C326.1
N110028547: length 2.8
  BOTTOM w0.102: R408.2 21.01,68.53 R410.2
  BOTTOM w0.109: U67.1 21.28,68.29 R408.2
N110029062: length 1.2
  BOTTOM w0.102: U67.4 R39.1
N110030307: length 4.6
  BOTTOM w0.102: R412.2 8.05,73.24 R411.2
  BOTTOM w0.109: R411.2 9.46,71.85 U70.24
N110030899: length 5.2
  BOTTOM w0.102: U70.22 8.14,69.32 8,69.46 R413.2 7.42,69.14 7.12,68.84 5.81,68.84 5.4,68.42 R449.2
N110063389: length 4.4
  BOTTOM w0.102: R422.1 152.49,88.21 154.12,88.21 154.47,88.56 J10.38
N110063392: length 4.9
  BOTTOM w0.102: R423.1 151.26,87.96 151.57,87.96 152.1,88.49 153.82,88.49 153.97,88.64 J10.40
N110098002: length 2.7
  TOP w0.381: R49.2 41.08,18.79 U13.3 39.94,18.79 R50.2
N110105894: length 2.9
  TOP w0.109: R429.2 14.41,38.15 14.12,38.15 13.71,37.74 13.71,37.36 13.42,37.07 U61.4
N110105900: length 1.5
  TOP w0.109: R430.2 13.9,38.75 13,37.85 U61.5
N110105915: length 2.6
  TOP w0.203: U61.1 13,35.85 U61.16 13,34.98 13.38,34.6 R435.2
N110106386: length 1.2
  TOP w0.109: R230.2 12.6,38.5 U61.6
N110106400: length 1.2
  TOP w0.109: R231.2 12.2,38.33 U61.7
N110106414: length 1.7
  TOP w0.109: R232.2 11.14,38.3 11.36,38.3 11.8,37.86 U61.8
N110106418: length 2.9
  TOP w0.109: U61.9 11.36,37.07 9.68,38.75 R233.2
N110115246: length 1.7
  TOP w0.254: U78.2 17.25,29.75 R238.2
N110122839: length 4
  BOTTOM w0.203: C332.2 26.1,101.91 25.79,101.6 25.79,100.25 25.06,99.51 U49.13
N110220095: length 2.2
  BOTTOM w0.254: R436.1 23.91,72.77 R437.1 22.81,72.78 U66.4
N110240993: length 2.5
  BOTTOM w0.203: C283.2 23.43,102.16 U49.11
N110241540: length 2.7
  BOTTOM w0.203: R278.1 25.84,97.47 24.59,98.71 U49.15
N110634243: length 3.2
  BOTTOM w0.203: U49.7 21.25,99.91 20.37,100.8 20.37,101.23 R446.1
N111139968: length 2
  TOP w0.109: R283.1 5.1,134.75 SW4.8
N111139982: length 1.9
  TOP w0.109: SW4.7 6.37,134.96 R284.1
N111139996: length 2
  TOP w0.109: SW4.6 7.64,134.78 R285.1
N111140010: length 2.1
  TOP w0.109: SW4.5 8.91,134.58 R286.1
N111151562: length 5.2
  BOTTOM w0.381: Q15.1 136.01,76.2 R452.2 133.51,77.51 Q13.3
N111153330: length 5.7
  BOTTOM w0.381: R34.1 136.04,79.56 135.95,79.65 R33.2 134.32,80.26 R36.2 ; R34.1 C343.1 ; R34.1 136.03,78.94 Q13.1
N112037494: length 2.5
  TOP w0.381: U12.4 69.28,38.09 R52.1 70.38,39.4 R46.2
N112037543: length 2.6
  TOP w0.381: R51.1 68.19,33.95 R47.2 69.32,33.99 U12.3
N112068055: length 2.3
  BOTTOM w0.109: R441.2 28.85,48.51 U80.5
N112068092: length 2.2
  BOTTOM w0.109: U80.6 28.2,48.08 R442.2
N112068114: length 2
  BOTTOM w0.109: U80.7 R443.2
N112246951: length 3.8
  TOP w0.381: Q17.3 179.55,124.19 Q16.1 177.36,125.26 R455.2
N112247388: length 2.8
  TOP w0.381: R456.2 179.41,119.73 R457.1 179.02,121.28 Q17.1
N112941127: length 1.3
  BOTTOM w0.109: U66.1 20.71,73.72 R458.2

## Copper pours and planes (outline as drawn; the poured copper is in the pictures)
GND on TOP: 167.22,98.46 171.49,98.46 172.06,97.89 172.06,85.8 171.32,85.06 163.66,85.06 163.34,85.39 163.34,94.58
GND on TOP: 115.25,29.84 119.77,29.84 120.12,29.5 121.64,29.5 122.32,30.17 122.32,31.18 121.82,31.68 121.16,31.68 121.08,31.77 121.08,38.17 122.87,39.97 128.1,39.97 129.45,38.61 129.45,19.28 132.34,16.39 132.34,10.81 131.34,9.81 126.01,9.81 118.5,17.32 109.45,17.32 108.73,18.05 108.73,19.98 108.52,20.19 108.01,20.19 107.97,20.16 107.19,20.16 106.91,20.43 106.91,23.39 107.39,23.87 110.79,23.87 114.11,27.2 114.11,31.47 114.38,31.73 114.82,31.73 114.9,31.65 114.9,30.19
GND on TOP: 187.25,73.14 192.47,73.14 192.59,73.02 192.59,71.93 192.39,71.73 187.25,71.73 187.04,71.93 187.04,72.93
GND on TOP: 140.91,98.89 150.26,98.89 150.63,98.52 150.63,91.77 147.51,88.65 138.6,88.65 136.72,86.77 136.72,84.48 138.38,82.83 138.38,80.65 138.77,80.26 147.45,80.26 148.62,79.08 148.62,74.83 145.66,71.87 134.94,71.87 130.84,75.96 130.84,88.82
GND on TOP: 51.06,24.69 55.92,24.69 56.26,24.36 56.26,23.44 56.15,23.33 54.36,23.33 53.77,22.74 53.77,19.97 53.66,19.86 51.7,19.86 50.96,20.6 50.02,20.6 49.82,20.4 49.82,20.03 49.65,19.86 47.87,19.86 47.45,20.28 47.45,20.99 48.18,21.71 49.67,21.71 50.06,22.1 50.06,23.69
GND on TOP: outline of 349 points within 0.51,0.51 209.49,151.89 ; 4 cut-outs
GND on TOP: 25.83,64.84 28.47,64.84 28.88,64.43 28.88,63.19 28.84,63.15 25.87,63.15 25.49,63.53 25.49,64.49
GND on TOP: 187.17,55.36 192.39,55.36 192.51,55.24 192.51,54.15 192.3,53.95 187.16,53.95 186.96,54.15 186.96,55.15
GND on TOP: 58.47,33.29 59.81,33.29 59.92,33.19 59.92,33.03 59.87,32.99 59.63,32.99 59.63,32.99 59.19,32.99 59.08,32.88 59.08,31.37 58.53,30.81 58.53,30.1 58.72,29.91 61.58,29.91 61.77,29.72 61.77,26.28 61.78,26.27 61.78,25.89 62.18,25.48 63.91,25.48 64.18,25.22 64.18,23.13 63.81,22.77 58.73,22.77 58.63,22.87 58.63,23.25 58.69,23.31 60.04,23.31 60.24,23.52 60.24,24.57 60.56,24.89 60.56,25.4 60.43,25.53 60.43,25.57 59.82,25.57 59.55,25.83 59.55,26.62 58.88,27.3 57.2,27.3 57.04,27.45 57.04,29.32 57.18,29.45 57.98,29.45 58.27,29.74 58.27,31.94 58.75,32.41 58.75,32.83 58.57,33.01 58.44,33.01 58.39,33.06 58.39,33.21
GND on TOP: 193.29,80.8 198,80.8 198.31,80.49 198.31,79.68 197.98,79.36 193.36,79.36 193.07,79.64 193.07,80.58
GND on TOP: 177.89,74.69 179.23,73.35 184.54,73.35 185.2,72.69 185.2,64.28 183.85,62.93 179.31,62.93 177.4,61.01 158,61.01 157.34,60.36 151.02,60.36 150.15,61.23 150.15,66.94 159.95,76.74 162.78,76.74 164.84,74.69
GND on TOP: 35.84,27.4 38.72,27.4 39.27,26.85 39.27,23.63 38.66,23.02 36.34,23.02 35.74,23.62 35.74,27.3
GND on TOP: 140.66,27.27 162.15,27.27 162.86,26.56 162.86,23.35 162.58,23.06 161.51,23.06 161.05,22.6 161.05,17.65 166.36,12.35 166.36,10.76 165.44,9.84 161.6,9.84 156.33,15.12 140.58,15.12 139.84,15.86 139.84,26.45
GND on TOP: 187.34,93.52 192.56,93.52 192.68,93.4 192.68,92.31 192.47,92.11 187.33,92.11 187.13,92.31 187.13,93.3
GND on TOP: 29.52,24.81 30.83,24.81 31.01,24.63 31.01,23.71 30.86,23.55 29.63,23.55 29.42,23.77 29.42,24.7
GND on BOTTOM: 158.36,111.34 161.81,111.34 161.94,111.21 161.94,110.81 161.79,110.66 161.6,110.66 161.47,110.52 161.47,107.85 161.4,107.79 160.55,107.79 160.04,108.3 158.51,108.3 158.27,108.54 158.27,111.25
GND on BOTTOM: 32.01,132.24 43.57,132.24 44.14,132.81 53.73,132.81 56.3,130.23 80.69,130.23 81.65,129.28 81.65,127.95 81.1,127.4 58.09,127.4 57.39,126.7 31.1,126.7 29.36,128.45 29.36,132.46 29.68,132.78 31.47,132.78
